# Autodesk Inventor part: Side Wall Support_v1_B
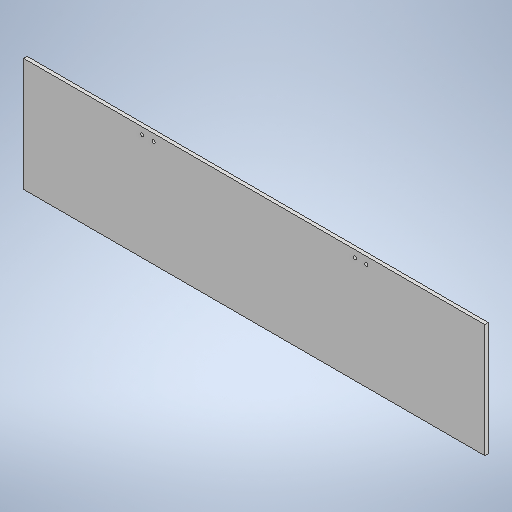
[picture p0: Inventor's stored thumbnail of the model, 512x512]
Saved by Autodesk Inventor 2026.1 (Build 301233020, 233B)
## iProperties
Created: 2026-10
Part Number: Side Wall Support_v1_B
Material: Generic
Document SubType Name: Modeling
Designer: hp
Density: 1 g/cm^3
Appearance: Default
Author: hp
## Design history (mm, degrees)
sketch "Sketch1"
  geometry: L1 (0, 0)-(700, 0); L2 (700, 160)-(0, 160); L3 (0, 160)-(0, 0); L4 (700, 160)-(700, 0); L5 (50, 160)-(50, 0)
  constraints: 10 end point, 2 point on line, 1 horizontal, 1 parallel, 1 perpendicular, 1 vertical
  dimensions: "d28" = 700 distance of L2.start L2.end; "d29" = 160 distance of L2.end L1.start; "d48" = 50 distance between parallel lines of L3 L5
extrude "Extrusion2" new body sketch "Sketch1" distance "d23" = 5; taper "d24" = 0 deg
sketch "Sketch4"
  geometry: 4 further points
hole "Hole1" sketch "Sketch4" at (217, 150), (233, 150), (517, 150), (533, 150) diameter "d49" = 4.5; stored, may be unused: countersink angle "d53" = 90 deg, drill point angle "d55" = 0 deg; dims "d50" = 6, "d51" = 4, "d52" = 2, "d54" = 8
body "Solid2"
